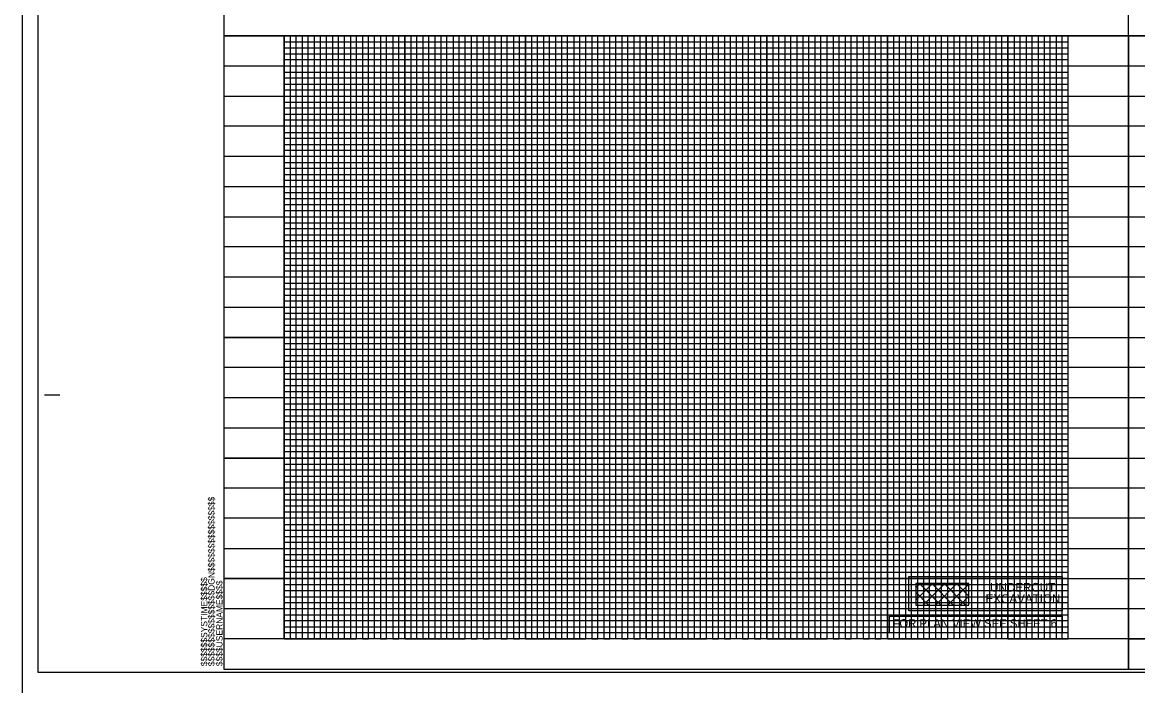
# Model space of a CAD drawing. Extents: x 1755181 to 1757273, y 729911 to 735411.
# Drawn here: x 1755181 to 1756105, y 731022 to 731572 of the extents above; entities that cross this region are included whole.
import ezdxf

# ---------------------------------------------------------------- set-up
doc = ezdxf.new("R2010")
doc.units = 0
for name, color, linetype in [('Prop Grid Mask', 7, 'Continuous'), ('Prop VPI Label', 7, 'Continuous'), ('Prop XS Undercut Exc Hatch', 7, 'Continuous'), ('Prop XSC Text', 7, 'Continuous'), ('Scratch_Level_3', 7, 'Continuous'), ('Sheet Cutting Line CELL', 7, 'Continuous'), ('Sheet DOT Grid CELL', 7, 'Continuous'), ('Sheet Plot Border Inside CELL', 7, 'Continuous'), ('Sheet Plot Border Outside CELL', 7, 'Continuous'), ('Sheet Profile CELL', 7, 'Continuous'), ('Sheet Profile Grid Major CELL', 7, 'Continuous'), ('Sheet Profile Grid Middle CELL', 7, 'Continuous'), ('Sheet Profile Grid Minor CELL', 7, 'Continuous')]:
    doc.layers.add(name, color=color, linetype=linetype)

msp = doc.modelspace()

# ---------------------------------------------------------------- linework, layer by layer
at = {"layer": 'Prop Grid Mask'}
for points in [[(1755915.45, 731112.5), (1756042.57, 731112.5), (1756042.57, 731084.17), (1755915.45, 731084.17)], [(1755921.31, 731088.85), (1755965.23, 731088.85), (1755965.23, 731106.6), (1755921.31, 731106.6)], [(1755899.57, 731079.63), (1756042.57, 731079.63), (1756042.57, 731065.9), (1755899.57, 731065.9)]]:
    msp.add_lwpolyline(points, close=True, dxfattribs=at)
at = {"layer": 'Prop XS Undercut Exc Hatch'}
for p, q in [((1755921.31, 731103.08), (1755924.83, 731106.6)), ((1755921.31, 731092.9), (1755935.01, 731106.6)), ((1755924.34, 731106.6), (1755942.1, 731088.85)), ((1755927.44, 731088.85), (1755945.2, 731106.6)), ((1755934.52, 731106.6), (1755952.28, 731088.85)), ((1755937.62, 731088.85), (1755955.38, 731106.6)), ((1755944.7, 731106.6), (1755962.46, 731088.85)), ((1755947.8, 731088.85), (1755965.23, 731106.28)), ((1755954.89, 731106.6), (1755965.23, 731096.26)), ((1755965.07, 731106.6), (1755965.23, 731106.44)), ((1755921.31, 731099.46), (1755931.91, 731088.85)), ((1755957.99, 731088.85), (1755965.23, 731096.1)), ((1755921.31, 731089.27), (1755921.73, 731088.85))]:
    msp.add_line(p, q, dxfattribs=at)
at = {"layer": 'Scratch_Level_3'}
for points in [[(1755347.67, 731560.78), (1756097.67, 731560.78), (1756097.67, 732085.78), (1755347.67, 732085.78)], [(1756097.67, 731560.78), (1756097.67, 732085.78), (1756647.63, 732085.78), (1756647.63, 731852.66), (1756847.68, 731852.66), (1756847.68, 731560.78)], [(1755347.67, 731035.78), (1756097.67, 731035.78), (1756097.67, 731560.78), (1755347.67, 731560.78)], [(1756097.67, 731035.78), (1756847.67, 731035.78), (1756847.67, 731560.78), (1756097.67, 731560.78)]]:
    msp.add_lwpolyline(points, close=True, dxfattribs=at)
at = {"layer": 'Sheet Cutting Line CELL'}
msp.add_line((1755180.67, 732110.78), (1755180.67, 731010.78), dxfattribs=at)
at = {"layer": 'Sheet DOT Grid CELL'}
for p, q in [((1755347.67, 731560.78), (1756847.56, 731560.78)), ((1755397.67, 731060.78), (1755397.67, 731560.78)), ((1755447.67, 731060.78), (1755447.67, 731560.78)), ((1755497.67, 731060.78), (1755497.67, 731560.78)), ((1755547.67, 731060.78), (1755547.67, 731560.78)), ((1755597.67, 731060.78), (1755597.67, 731560.78)), ((1755647.67, 731060.78), (1755647.67, 731560.78)), ((1755697.67, 731060.78), (1755697.67, 731560.78)), ((1755747.67, 731060.78), (1755747.67, 731560.78)), ((1755797.67, 731060.78), (1755797.67, 731560.78)), ((1755847.67, 731060.78), (1755847.67, 731560.78)), ((1755897.67, 731060.78), (1755897.67, 731560.78)), ((1755947.67, 731060.78), (1755947.67, 731560.78)), ((1755997.67, 731060.78), (1755997.67, 731560.78)), ((1756047.67, 731060.78), (1756047.67, 731560.78)), ((1756097.67, 731060.78), (1756097.67, 731560.78)), ((1756047.68, 731310.78), (1755347.67, 731310.78)), ((1756047.68, 731260.78), (1755347.67, 731260.78)), ((1756047.68, 731210.78), (1755347.67, 731210.78)), ((1756047.68, 731160.78), (1755347.67, 731160.78)), ((1756047.68, 731110.78), (1755347.67, 731110.78))]:
    msp.add_line(p, q, dxfattribs=at)
at = {"layer": 'Sheet Plot Border Inside CELL'}
msp.add_lwpolyline([(1755193.67, 731033.23), (1756860.17, 731033.23), (1756860.17, 732088.33), (1755193.67, 732088.33)], close=True, dxfattribs=at)
at = {"layer": 'Sheet Plot Border Outside CELL'}
msp.add_lwpolyline([(1755180.67, 731010.78), (1756864.67, 731010.78), (1756864.67, 732110.78), (1755180.67, 732110.78)], close=True, dxfattribs=at)
at = {"layer": 'Sheet Profile CELL'}
for p, q in [((1755347.67, 731560.78), (1756847.67, 731560.78)), ((1756097.67, 731560.78), (1756097.67, 731060.78)), ((1755199.17, 731263.28), (1755211.67, 731263.28)), ((1756847.67, 731060.78), (1755347.67, 731060.78)), ((1755347.67, 731035.78), (1756847.67, 731035.78)), ((1755347.67, 731035.78), (1755347.67, 731035.78))]:
    msp.add_line(p, q, dxfattribs=at)
msp.add_lwpolyline([(1756847.67, 732085.78), (1755347.67, 732085.78), (1755347.67, 731035.78), (1756847.67, 731035.78)], close=True, dxfattribs=at)
msp.add_lwpolyline([(1755385.17, 731035.78), (1755385.17, 731035.78)], dxfattribs=at)
at = {"layer": 'Sheet Profile Grid Major CELL'}
for p, q in [((1755847.67, 731560.78), (1755897.67, 731560.78)), ((1755947.67, 731560.78), (1755997.67, 731560.78)), ((1756047.67, 731560.78), (1756097.67, 731560.78)), ((1755347.67, 731060.78), (1755347.67, 731060.78))]:
    msp.add_line(p, q, dxfattribs=at)
for points in [[(1755397.67, 731560.78), (1755397.67, 731060.78), (1755447.67, 731060.78), (1755447.67, 731560.78), (1755497.67, 731560.78), (1755497.67, 731060.78), (1755547.67, 731060.78), (1755547.67, 731560.78), (1755597.67, 731560.78), (1755597.67, 731060.78), (1755647.67, 731060.78), (1755647.67, 731560.78), (1755697.67, 731560.78), (1755697.67, 731060.78), (1755747.67, 731060.78), (1755747.67, 731560.78), (1755797.67, 731560.78), (1755797.67, 731060.78), (1755847.67, 731060.78), (1755847.67, 731560.78), (1755897.67, 731560.78), (1755897.67, 731060.78), (1755947.67, 731060.78), (1755947.67, 731560.78), (1755997.67, 731560.78), (1755997.67, 731060.78), (1756047.67, 731060.78), (1756047.67, 731560.78), (1756097.67, 731560.78), (1756097.67, 731060.78), (1756147.67, 731060.78)], [(1755347.67, 731510.78), (1756847.71, 731510.78)], [(1756847.71, 731460.78), (1755347.67, 731460.78), (1755347.67, 731410.78), (1756847.71, 731410.78)], [(1756847.67, 731360.78), (1755347.67, 731360.78), (1755347.67, 731310.78), (1756847.67, 731310.78)], [(1756847.67, 731260.78), (1755347.67, 731260.78), (1755347.67, 731210.78), (1756847.67, 731210.78)], [(1756847.67, 731160.78), (1755347.67, 731160.78), (1755347.67, 731160.78), (1755347.67, 731110.78), (1756847.67, 731110.78)], [(1756847.67, 731060.78), (1755347.67, 731060.78)]]:
    msp.add_lwpolyline(points, dxfattribs=at)
at = {"layer": 'Sheet Profile Grid Middle CELL'}
for p, q in [((1755422.67, 731560.78), (1755422.67, 731060.78)), ((1755472.67, 731060.78), (1755472.67, 731560.78)), ((1755522.67, 731560.78), (1755522.67, 731060.78)), ((1755572.67, 731060.78), (1755572.67, 731560.78)), ((1755622.67, 731560.78), (1755622.67, 731060.78)), ((1755672.67, 731060.78), (1755672.67, 731560.78)), ((1755722.67, 731560.78), (1755722.67, 731060.78)), ((1755772.67, 731060.78), (1755772.67, 731560.78)), ((1755822.67, 731560.78), (1755822.67, 731060.78)), ((1755872.67, 731060.78), (1755872.67, 731560.78)), ((1755922.67, 731560.78), (1755922.67, 731060.78)), ((1755972.67, 731060.78), (1755972.67, 731560.78)), ((1756022.67, 731560.78), (1756022.67, 731060.78)), ((1755347.67, 731535.78), (1756847.66, 731535.78))]:
    msp.add_line(p, q, dxfattribs=at)
for points in [[(1756847.71, 731485.78), (1755347.67, 731485.78), (1755347.67, 731435.78), (1756847.71, 731435.78)], [(1756847.66, 731385.78), (1755347.67, 731385.78), (1755347.67, 731335.78), (1756847.67, 731335.78)], [(1756847.67, 731285.78), (1755347.67, 731285.78), (1755347.67, 731235.78), (1756847.67, 731235.78)], [(1756847.67, 731185.78), (1755347.67, 731185.78), (1755347.67, 731135.78), (1756847.67, 731135.78)], [(1756847.67, 731085.78), (1755347.67, 731085.78)]]:
    msp.add_lwpolyline(points, dxfattribs=at)
at = {"layer": 'Sheet Profile Grid Minor CELL'}
for p, q in [((1755927.67, 731560.78), (1755927.67, 731060.78)), ((1755932.67, 731060.78), (1755932.67, 731560.78)), ((1755937.67, 731560.78), (1755937.67, 731060.78)), ((1755942.67, 731060.78), (1755942.67, 731560.78)), ((1755952.67, 731560.78), (1755952.67, 731060.78)), ((1755957.67, 731060.78), (1755957.67, 731560.78)), ((1755962.67, 731560.78), (1755962.67, 731060.78)), ((1755967.67, 731060.78), (1755967.67, 731560.78)), ((1755977.67, 731560.78), (1755977.67, 731060.78)), ((1755982.67, 731060.78), (1755982.67, 731560.78)), ((1755987.67, 731560.78), (1755987.67, 731060.78)), ((1755992.67, 731060.78), (1755992.67, 731560.78)), ((1756002.67, 731560.78), (1756002.67, 731060.78)), ((1756007.67, 731060.78), (1756007.67, 731560.78)), ((1756012.67, 731560.78), (1756012.67, 731060.78)), ((1756017.67, 731060.78), (1756017.67, 731560.78)), ((1756027.67, 731560.78), (1756027.67, 731060.78)), ((1756032.67, 731060.78), (1756032.67, 731560.78)), ((1756037.67, 731560.78), (1756037.67, 731060.78)), ((1756042.67, 731060.78), (1756042.67, 731560.78)), ((1755397.67, 731555.78), (1756047.68, 731555.78)), ((1756047.68, 731550.62), (1755397.67, 731550.43)), ((1755397.67, 731545.78), (1756047.68, 731545.78)), ((1756047.68, 731425.78), (1755397.67, 731425.78)), ((1756047.68, 731420.78), (1755397.67, 731420.78)), ((1756047.68, 731415.78), (1755397.67, 731415.78)), ((1755397.67, 731405.78), (1756047.68, 731405.78)), ((1756047.68, 731400.78), (1755397.67, 731400.78)), ((1755397.67, 731395.78), (1756047.68, 731395.78)), ((1756047.68, 731375.78), (1755397.67, 731375.78)), ((1755397.67, 731370.78), (1756047.68, 731370.78)), ((1756047.68, 731350.78), (1755397.67, 731350.78)), ((1755397.67, 731345.78), (1756047.68, 731345.78)), ((1756047.68, 731325.78), (1755397.67, 731325.78)), ((1755397.67, 731320.78), (1756047.68, 731320.78)), ((1756047.68, 731315.78), (1755397.67, 731315.78)), ((1755397.67, 731305.78), (1756047.68, 731305.78)), ((1756047.68, 731300.78), (1755397.67, 731300.78)), ((1755397.67, 731295.78), (1756047.68, 731295.78)), ((1756047.68, 731290.78), (1755397.67, 731290.78)), ((1755397.67, 731280.78), (1756047.68, 731280.78)), ((1756047.68, 731275.78), (1755397.67, 731275.78)), ((1755397.67, 731270.78), (1756047.68, 731270.78)), ((1756047.68, 731265.78), (1755397.67, 731265.78)), ((1755397.67, 731255.78), (1756047.68, 731255.78)), ((1756047.68, 731250.78), (1755397.67, 731250.78)), ((1755397.67, 731245.78), (1756047.68, 731245.78)), ((1756047.68, 731240.78), (1755397.67, 731240.78)), ((1755397.67, 731230.78), (1756047.68, 731230.78)), ((1756047.68, 731225.78), (1755397.67, 731225.78)), ((1755397.67, 731220.78), (1756047.68, 731220.78)), ((1756047.68, 731215.78), (1755397.67, 731215.78)), ((1755397.67, 731205.78), (1756047.68, 731205.78)), ((1756047.68, 731200.78), (1755397.67, 731200.78)), ((1755397.67, 731195.78), (1756047.68, 731195.78)), ((1756047.68, 731190.78), (1755397.67, 731190.78)), ((1755397.67, 731180.78), (1756047.68, 731180.78)), ((1756047.68, 731175.78), (1755397.67, 731175.78)), ((1756047.68, 731170.78), (1755397.67, 731170.78)), ((1756047.68, 731165.78), (1755397.67, 731165.78)), ((1755397.67, 731155.78), (1756047.68, 731155.78)), ((1756047.68, 731150.78), (1755397.67, 731150.78)), ((1755397.67, 731145.78), (1756047.68, 731145.78)), ((1756047.68, 731140.78), (1755397.67, 731140.78)), ((1755397.67, 731130.78), (1756047.68, 731130.78)), ((1756047.68, 731125.78), (1755397.67, 731125.78)), ((1755397.67, 731120.78), (1756047.68, 731120.78)), ((1756047.68, 731115.78), (1755397.67, 731115.78)), ((1755397.67, 731105.78), (1756047.68, 731105.78)), ((1756047.68, 731100.78), (1755397.67, 731100.78)), ((1755397.67, 731095.78), (1756047.68, 731095.78)), ((1756047.68, 731090.78), (1755397.67, 731090.78)), ((1755397.67, 731080.78), (1756047.68, 731080.78)), ((1756047.68, 731075.78), (1755397.67, 731075.78)), ((1755397.67, 731070.78), (1756047.68, 731070.78))]:
    msp.add_line(p, q, dxfattribs=at)
for points in [[(1755402.67, 731560.78), (1755402.67, 731060.78), (1755407.67, 731060.78), (1755407.67, 731560.78), (1755412.67, 731560.78), (1755412.67, 731060.78), (1755417.67, 731060.78), (1755417.67, 731560.78), (1755427.67, 731560.78), (1755427.67, 731060.78), (1755432.67, 731060.78), (1755432.67, 731560.78), (1755437.67, 731560.78), (1755437.67, 731060.78), (1755442.67, 731060.78), (1755452.67, 731060.78), (1755457.67, 731060.78), (1755457.67, 731560.78), (1755462.67, 731560.78), (1755462.67, 731060.78), (1755467.67, 731060.78), (1755467.67, 731560.78), (1755477.67, 731560.78), (1755477.67, 731060.78), (1755482.67, 731060.78), (1755482.67, 731560.78), (1755487.67, 731560.78), (1755487.67, 731060.78), (1755492.67, 731060.78), (1755492.67, 731560.78), (1755502.67, 731560.78), (1755502.67, 731060.78), (1755507.67, 731060.78), (1755507.67, 731560.78), (1755512.67, 731560.78), (1755512.67, 731060.78), (1755517.67, 731060.78), (1755517.67, 731560.78), (1755527.67, 731560.78), (1755527.67, 731060.78), (1755532.67, 731060.78), (1755532.67, 731560.78), (1755537.67, 731560.78), (1755537.67, 731060.78), (1755542.67, 731060.78), (1755542.67, 731560.78), (1755552.67, 731560.78), (1755552.67, 731060.78), (1755557.67, 731060.78), (1755557.67, 731560.78), (1755562.67, 731560.78), (1755562.67, 731060.78), (1755567.67, 731060.78), (1755567.67, 731560.78), (1755577.67, 731560.78), (1755577.67, 731060.78), (1755582.67, 731060.78), (1755582.67, 731560.78), (1755587.67, 731560.78), (1755587.67, 731060.78), (1755592.67, 731060.78), (1755592.67, 731560.78), (1755602.67, 731560.78), (1755602.67, 731060.78), (1755607.67, 731060.78), (1755607.67, 731560.78), (1755612.67, 731560.78), (1755612.67, 731060.78)], [(1755442.67, 731060.78), (1755442.67, 731560.78), (1755452.67, 731560.78), (1755452.67, 731060.78)], [(1755612.67, 731060.78), (1755617.67, 731060.78), (1755617.67, 731560.78), (1755627.67, 731560.78), (1755627.67, 731060.78), (1755632.67, 731060.78), (1755632.67, 731560.78), (1755637.67, 731560.78), (1755637.67, 731060.78), (1755642.67, 731060.78), (1755642.67, 731560.78), (1755652.67, 731560.78), (1755652.67, 731060.78), (1755657.67, 731060.78), (1755657.67, 731560.78), (1755662.67, 731560.78), (1755662.67, 731060.78), (1755667.67, 731060.78), (1755667.67, 731560.78), (1755677.67, 731560.78), (1755677.67, 731060.78), (1755682.67, 731060.78), (1755682.67, 731560.78), (1755687.67, 731560.78), (1755687.67, 731060.78), (1755692.67, 731060.78), (1755692.67, 731560.78), (1755702.67, 731560.78), (1755702.67, 731060.78), (1755707.67, 731060.78), (1755707.67, 731560.78), (1755712.67, 731560.78), (1755712.67, 731060.78), (1755717.67, 731060.78), (1755717.67, 731560.78), (1755727.67, 731560.78), (1755727.67, 731060.78), (1755732.67, 731060.78), (1755732.67, 731560.78), (1755737.67, 731560.78), (1755737.67, 731060.78), (1755742.67, 731060.78), (1755742.67, 731560.78), (1755752.67, 731560.78), (1755752.67, 731060.78), (1755757.67, 731060.78), (1755757.67, 731560.78), (1755762.67, 731560.78), (1755762.67, 731060.78), (1755767.67, 731060.78), (1755767.67, 731560.78), (1755777.67, 731560.78), (1755777.67, 731060.78), (1755782.67, 731060.78), (1755782.67, 731560.78), (1755787.67, 731560.78), (1755787.67, 731060.78), (1755792.67, 731060.78), (1755792.67, 731560.78), (1755802.67, 731560.78), (1755802.67, 731060.78), (1755807.67, 731060.78), (1755807.67, 731560.78), (1755812.67, 731560.78), (1755812.67, 731060.78), (1755817.67, 731060.78), (1755817.67, 731560.78), (1755827.67, 731560.78), (1755827.67, 731060.78), (1755832.67, 731060.78), (1755832.67, 731560.78), (1755837.67, 731560.78), (1755837.67, 731060.78), (1755842.67, 731060.78), (1755842.67, 731560.78), (1755852.67, 731560.78), (1755852.67, 731060.78), (1755857.67, 731060.78), (1755857.67, 731560.78), (1755862.67, 731560.78), (1755862.67, 731060.78), (1755867.67, 731060.78), (1755867.67, 731560.78), (1755877.67, 731560.78), (1755877.67, 731060.78), (1755882.67, 731060.78), (1755882.67, 731560.78), (1755887.67, 731560.78), (1755887.67, 731060.78), (1755892.67, 731060.78), (1755892.67, 731560.78), (1755902.67, 731560.78), (1755902.67, 731060.78), (1755907.67, 731060.78), (1755907.67, 731560.78), (1755912.67, 731560.78), (1755912.67, 731060.78), (1755917.67, 731060.78), (1755917.67, 731560.78), (1755927.67, 731560.78)], [(1756047.68, 731540.78), (1755397.67, 731540.78), (1755397.67, 731530.78), (1756047.68, 731530.78)], [(1756047.68, 731525.78), (1755397.67, 731525.78), (1755397.67, 731520.78), (1756047.68, 731520.78)], [(1756047.68, 731515.78), (1755397.67, 731515.78), (1755397.67, 731505.78), (1756047.68, 731505.78)], [(1756047.68, 731500.78), (1755397.67, 731500.78), (1755397.67, 731495.78), (1756047.68, 731495.78)], [(1756047.68, 731490.78), (1755397.67, 731490.78), (1755397.67, 731480.78), (1756047.68, 731480.78)], [(1756047.68, 731475.78), (1755397.67, 731475.78), (1755397.67, 731470.78), (1756047.68, 731470.78)], [(1756047.68, 731465.78), (1755397.67, 731465.78), (1755397.67, 731455.78), (1756047.68, 731455.78)], [(1756047.68, 731450.68), (1755397.77, 731450.68), (1755397.77, 731445.78), (1756047.68, 731445.78)], [(1756047.68, 731440.78), (1755397.67, 731440.78), (1755397.67, 731430.78), (1756047.68, 731430.78)], [(1756047.68, 731390.78), (1755397.67, 731390.78), (1755397.67, 731380.78), (1756047.68, 731380.78)], [(1756047.68, 731365.78), (1755397.67, 731365.78), (1755397.67, 731355.78), (1756047.68, 731355.78)], [(1756047.68, 731340.78), (1755397.67, 731340.78), (1755397.67, 731330.78), (1756047.68, 731330.78)], [(1756047.68, 731065.78), (1755397.67, 731065.78)]]:
    msp.add_lwpolyline(points, dxfattribs=at)

# ---------------------------------------------------------------- texts
at = {"layer": 'Prop VPI Label'}
msp.add_text('FOR PLAN VIEW SEE SHEET 6', height=7, dxfattribs=at).set_placement((1755901.97, 731070.14))
at = {"layer": 'Prop XSC Text'}
for s, p in [('UNDERCUT', (1755982.81, 731100.01)), ('EXCAVATION', (1755979.03, 731090.58))]:
    msp.add_text(s, height=7.2, dxfattribs=at).set_placement(p)
at = {"layer": 'Sheet Profile CELL'}
for s, p in [('$$$$$$$$$$$$$$$$DGN$$$$$$$$$$$$$$$$', (1755340.03, 731038.16)), ('$$$$$$SYSTIME$$$$$', (1755333.98, 731038.16)), ('$$$$USERNAME$$$$', (1755346.61, 731038.17))]:
    msp.add_text(s, height=5.25, rotation=90, dxfattribs=at).set_placement(p)

doc.saveas('drawing.dxf')
